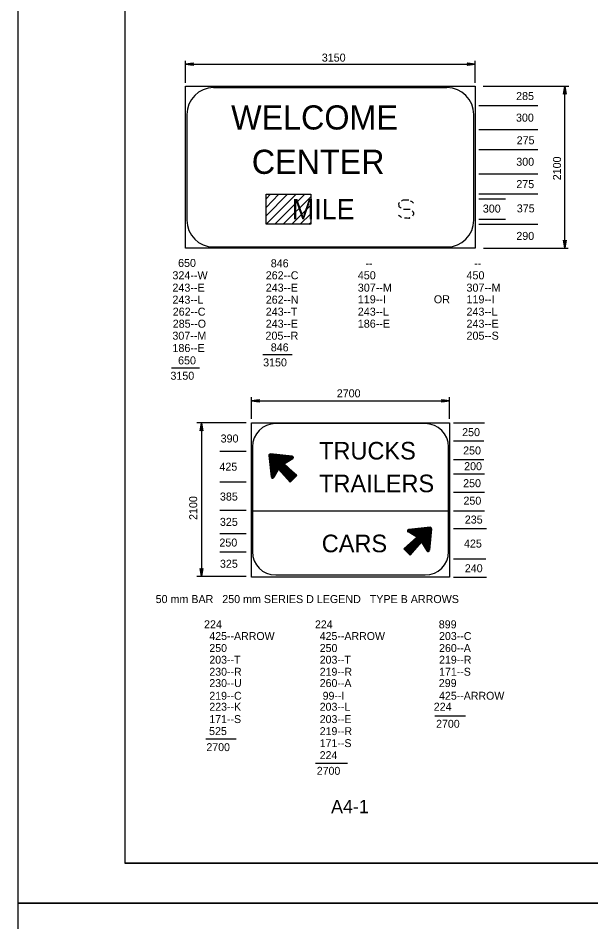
# Model space of a CAD drawing. Extents: x 638689 to 652291, y 298458 to 299646.
# Drawn here: x 651386.3 to 651601.1, y 299044.7 to 299383.4 of the extents above; entities that cross this region are included whole.
import ezdxf

# ---------------------------------------------------------------- set-up
doc = ezdxf.new("R2010")
doc.units = 0
for name, color, linetype in [('1', 7, 'Continuous'), ('2', 7, 'Continuous'), ('3', 7, 'Continuous'), ('PLT-BNDY', 7, 'Continuous')]:
    doc.layers.add(name, color=color, linetype=linetype)

# ---------------------------------------------------------------- blocks, each defined once
blk = doc.blocks.new('RARROW')
at = {"layer": '3'}
blk.add_lwpolyline([(-2.2695, 0.285), (-2.184875, 0.12075), (0, 0), (-2.2695, 0.285), (-2.38575, 0.384625), (0, 0), (-2.183125, -0.108), (-2.262875, -0.2705), (0, 0), (-2.38575, -0.379125), (-2.262875, -0.2705)], dxfattribs=at)

msp = doc.modelspace()

# ---------------------------------------------------------------- linework, layer by layer
at = {"layer": '1'}
for p, q in [((651426.31, 299630.75), (651426.31, 299066.75)), ((652212.31, 299066.75), (651426.31, 299066.75)), ((651426.31, 299066.75), (652012.31, 299066.75))]:
    msp.add_line(p, q, dxfattribs=at)
at = {"layer": '2'}
for p, q in [((651449.06, 299359.12), (651449.06, 299367.37)), ((651557.69, 299359.12), (651557.69, 299367.37)), ((651449.06, 299366.12), (651557.69, 299366.12)), ((651449.06, 299357.87), (651557.69, 299357.87)), ((651449.06, 299297.12), (651449.06, 299357.87)), ((651547.06, 299357.25), (651459.56, 299357.25)), ((651557.69, 299357.87), (651557.69, 299297.12)), ((651560.69, 299357.87), (651592.75, 299357.87)), ((651591.25, 299297.12), (651591.25, 299357.87)), ((651559.06, 299350.62), (651581.16, 299350.62)), ((651449.56, 299347.12), (651449.56, 299307.75)), ((651557.19, 299307.75), (651557.19, 299347.12)), ((651559.06, 299341.62), (651581.16, 299341.62)), ((651559.06, 299334.12), (651581.16, 299334.12)), ((651559.06, 299325), (651581.16, 299325)), ((651559.06, 299317.5), (651581.16, 299317.5)), ((651559.06, 299315.62), (651569.06, 299315.62)), ((651559.06, 299308), (651569.06, 299308)), ((651559.06, 299306.12), (651581.16, 299306.12)), ((651557.69, 299297.12), (651449.06, 299297.12)), ((651459.56, 299297.62), (651547.06, 299297.62)), ((651560.81, 299297.12), (651592.5, 299297.12)), ((651473.8, 299223.87), (651473.8, 299229.37)), ((651471.8, 299220.99), (651461.92, 299220.99)), ((651471.8, 299209.49), (651461.92, 299209.49)), ((651473.8, 299197.37), (651473.8, 299200.99)), ((651471.8, 299198.87), (651461.92, 299198.87)), ((651473.8, 299198.74), (651547.67, 299198.74)), ((651471.8, 299190.12), (651461.92, 299190.12)), ((651471.8, 299183.24), (651461.92, 299183.24)), ((651542.55, 299121.99), (651554.05, 299121.99)), ((651456.67, 299113.37), (651468.05, 299113.37)), ((651497.8, 299104.24), (651509.8, 299104.24))]:
    msp.add_line(p, q, dxfattribs=at)
msp.add_lwpolyline([(651479.31, 299306.12), (651479.31, 299317.37), (651496.06, 299317.37), (651496.06, 299306.12)], close=True, dxfattribs=at)
for points in [[(651479.31, 299306.12), (651490.56, 299317.37)], [(651479.31, 299309.25), (651487.31, 299317.37)], [(651479.31, 299312.37), (651484.06, 299317.37)], [(651479.31, 299315.62), (651480.94, 299317.37)], [(651482.56, 299306.12), (651493.81, 299317.37)], [(651485.69, 299306.12), (651496.06, 299316.37)], [(651488.94, 299306.12), (651496.06, 299313.25)], [(651492.06, 299306.12), (651496.06, 299310)], [(651495.31, 299306.12), (651496.06, 299306.75)], [(651473.8, 299231.74), (651548.05, 299231.74), (651548.05, 299226.62), (651548.05, 299219.99), (651548.05, 299214.99), (651548.05, 299208.37), (651548.05, 299203.24), (651548.05, 299198.37), (651548.05, 299187.37), (651548.05, 299173.87), (651473.8, 299173.87), (651473.8, 299189.37), (651473.8, 299196.12), (651473.8, 299203.24), (651473.8, 299211.87), (651473.8, 299222.62), (651473.8, 299231.74)]]:
    msp.add_lwpolyline(points, dxfattribs=at)
for centre, start, end in [((651459.64, 299347.25), 90, 180), ((651547.12, 299347.25), 0, 90), ((651459.64, 299307.66), 180, 270), ((651547.12, 299307.66), 270, 0)]:
    msp.add_arc(centre, 10.05, start, end, dxfattribs=at)
for points in [[(651529.31, 299314.25), (651529.19, 299314.12), (651529.06, 299314), (651529.06, 299313.12), (651529.19, 299312.62), (651529.69, 299312.37), (651529.94, 299312.12)], [(651532.81, 299315.12), (651532.56, 299315.12), (651532.19, 299315.12), (651530.94, 299315.12), (651530.69, 299315.12), (651530.06, 299314.75)], [(651534.56, 299314), (651534.06, 299314.5), (651533.44, 299314.75)], [(651530.06, 299308.62), (651529.94, 299308.75), (651529.56, 299309), (651528.94, 299309.5)], [(651530.81, 299311.75), (651531.19, 299311.75), (651531.69, 299311.75), (651532.31, 299311.75), (651532.81, 299311.75), (651533.19, 299311.75), (651533.31, 299311.62)], [(651534.06, 299311.12), (651534.31, 299310.87), (651534.44, 299310.62), (651534.56, 299310.5), (651534.56, 299310), (651534.44, 299309.62), (651534.19, 299309.12)], [(651533.06, 299308.37), (651533.19, 299308.5), (651532.81, 299308.37), (651532.19, 299308.37), (651531.56, 299308.37), (651531.19, 299308.37)]]:
    msp.add_spline(points, degree=3, dxfattribs=at)
at = {"layer": '3'}
for p, q in [((651478.06, 299257.37), (651489.06, 299257.37)), ((651443.81, 299252.37), (651454.31, 299252.37)), ((651473.8, 299233.24), (651473.8, 299241.37)), ((651548.05, 299233.24), (651548.05, 299241.37)), ((651473.8, 299239.99), (651548.05, 299239.99)), ((651471.8, 299231.74), (651453.3, 299231.74)), ((651455.05, 299231.74), (651455.05, 299174.12)), ((651549.55, 299231.74), (651561.14, 299231.74)), ((651549.55, 299224.99), (651560.94, 299224.99)), ((651474.17, 299222.62), (651474.17, 299183.37)), ((651547.67, 299183.37), (651547.67, 299222.62)), ((651480.3, 299219.49), (651481.17, 299211.49)), ((651480.42, 299219.87), (651480.42, 299219.87)), ((651480.42, 299219.87), (651480.42, 299219.87)), ((651489.05, 299219.24), (651480.92, 299220.12)), ((651480.92, 299219.62), (651480.92, 299219.62)), ((651486.05, 299216.37), (651489.3, 299218.37)), ((651488.8, 299218.74), (651488.8, 299218.74)), ((651489.67, 299218.74), (651489.67, 299218.74)), ((651489.67, 299218.74), (651489.67, 299218.74)), ((651549.55, 299217.99), (651560.94, 299217.99)), ((651483.92, 299214.37), (651482.17, 299211.24)), ((651483.92, 299214.37), (651483.92, 299214.37)), ((651483.92, 299214.37), (651488.3, 299209.49)), ((651485.05, 299215.37), (651485.05, 299215.37)), ((651486.05, 299216.37), (651486.05, 299216.37)), ((651490.8, 299211.99), (651486.05, 299216.37)), ((651481.8, 299211.49), (651481.8, 299211.49)), ((651481.8, 299210.74), (651481.8, 299210.74)), ((651481.8, 299210.74), (651481.8, 299210.74)), ((651488.3, 299209.49), (651490.8, 299211.99)), ((651490.8, 299211.99), (651490.8, 299211.99)), ((651549.55, 299212.62), (651561.14, 299212.62)), ((651488.3, 299209.49), (651488.3, 299209.49)), ((651549.55, 299205.74), (651561.14, 299205.74)), ((651549.55, 299198.74), (651561.14, 299198.74)), ((651532.17, 299191.12), (651532.17, 299191.12)), ((651532.17, 299191.12), (651532.17, 299191.12)), ((651535.8, 299188.87), (651532.55, 299190.87)), ((651540.8, 299192.62), (651532.8, 299191.74)), ((651532.8, 299191.12), (651532.8, 299191.12)), ((651540.67, 299183.99), (651541.42, 299191.99)), ((651540.8, 299191.99), (651540.8, 299191.99)), ((651549.55, 299192.12), (651561.9, 299192.12)), ((651535.8, 299188.87), (651530.92, 299184.49)), ((651533.3, 299182.12), (651537.55, 299186.99)), ((651535.8, 299188.87), (651535.8, 299188.87)), ((651536.67, 299187.87), (651536.67, 299187.87)), ((651537.55, 299186.99), (651537.55, 299186.99)), ((651537.55, 299186.99), (651539.55, 299183.74)), ((651530.92, 299184.49), (651530.92, 299184.49)), ((651530.92, 299184.49), (651533.3, 299182.12)), ((651540.05, 299184.12), (651540.05, 299184.12)), ((651540.05, 299183.37), (651540.05, 299183.37)), ((651540.05, 299183.37), (651540.05, 299183.37)), ((651533.3, 299182.12), (651533.3, 299182.12)), ((651549.55, 299180.74), (651561.71, 299180.74)), ((651471.8, 299174.12), (651453.3, 299174.12)), ((651549.55, 299173.87), (651561.9, 299173.87))]:
    msp.add_line(p, q, dxfattribs=at)
for points in [[(651538.92, 299231.49), (651483.05, 299231.49)], [(651480.67, 299219.62), (651481.42, 299211.62), (651481.42, 299211.24), (651481.92, 299210.99), (651482.05, 299211.24), (651483.92, 299214.87), (651484.3, 299214.62), (651488.42, 299209.87), (651490.67, 299212.12), (651485.8, 299216.24), (651485.92, 299216.49), (651489.3, 299218.49), (651489.55, 299218.74), (651489.42, 299218.99), (651489.05, 299218.99), (651480.92, 299219.87), (651480.67, 299219.87), (651480.67, 299219.62), (651480.8, 299219.62), (651481.8, 299211.24), (651483.92, 299214.99), (651488.42, 299210.12), (651490.42, 299211.99), (651485.55, 299216.49), (651489.42, 299218.74), (651480.8, 299219.74), (651481.92, 299211.74), (651483.92, 299215.24), (651488.42, 299210.24), (651490.3, 299211.99), (651485.3, 299216.49), (651489.05, 299218.74), (651480.92, 299219.62), (651481.92, 299211.99), (651483.92, 299215.37), (651488.55, 299210.49), (651490.05, 299211.99), (651485.17, 299216.49), (651488.55, 299218.74), (651481.05, 299219.49), (651481.92, 299212.49), (651483.92, 299215.37), (651488.55, 299210.74), (651489.8, 299211.99), (651485.05, 299216.62), (651488.3, 299218.62), (651481.17, 299219.24), (651482.05, 299212.87), (651483.92, 299215.49), (651488.55, 299210.99), (651489.67, 299212.12), (651484.92, 299216.62), (651487.92, 299218.37), (651481.42, 299218.99), (651482.3, 299213.24), (651483.92, 299215.62), (651488.55, 299211.24), (651489.55, 299212.12), (651484.92, 299216.62), (651487.42, 299218.12), (651481.55, 299218.99), (651482.42, 299213.87), (651483.92, 299215.99), (651488.55, 299211.49), (651489.3, 299212.12), (651484.8, 299216.62), (651487.17, 299217.99), (651481.8, 299218.74), (651482.55, 299214.24), (651483.8, 299216.24), (651488.55, 299211.74), (651489.05, 299212.12), (651484.55, 299216.62), (651486.67, 299217.87), (651481.92, 299218.62), (651482.55, 299214.49), (651483.8, 299216.37), (651488.55, 299211.87), (651488.8, 299212.12), (651484.42, 299216.62), (651486.17, 299217.87), (651482.17, 299218.49), (651482.55, 299214.99), (651483.8, 299216.62), (651488.55, 299211.99), (651488.55, 299211.99), (651484.17, 299216.62), (651485.8, 299217.74), (651482.42, 299218.12), (651482.67, 299215.37), (651483.8, 299216.62), (651488.55, 299211.99), (651483.92, 299216.74), (651485.42, 299217.74), (651482.55, 299217.99), (651482.8, 299215.62), (651483.8, 299216.74), (651486.05, 299214.62), (651483.8, 299216.87), (651485.17, 299217.62), (651482.67, 299217.87)], [(651482.67, 299217.87), (651483.05, 299216.24), (651484.92, 299217.49), (651482.8, 299217.74), (651483.17, 299216.49), (651484.67, 299217.49), (651483.05, 299217.49), (651483.17, 299216.62), (651484.17, 299217.49), (651483.17, 299217.49), (651483.17, 299216.87), (651483.8, 299217.37), (651483.17, 299217.37), (651483.3, 299217.37), (651483.55, 299217.37)], [(651540.8, 299192.37), (651532.92, 299191.49), (651532.55, 299191.49), (651532.42, 299191.12), (651532.55, 299190.99), (651536.05, 299188.87), (651536.05, 299188.87), (651531.17, 299184.49), (651533.42, 299182.24), (651537.42, 299186.99), (651537.67, 299186.99), (651539.67, 299183.74), (651540.05, 299183.49), (651540.17, 299183.74), (651540.3, 299183.99), (651541.17, 299192.12), (651541.17, 299192.24), (651540.92, 299192.49), (651540.8, 299192.12), (651532.55, 299191.24), (651536.3, 299188.87), (651531.3, 299184.49), (651533.3, 299182.24), (651537.67, 299187.49), (651540.05, 299183.74), (651541.05, 299192.24), (651532.92, 299191.12), (651536.42, 299188.87), (651531.55, 299184.49), (651533.3, 299182.74), (651537.67, 299187.62), (651539.92, 299184.12), (651540.8, 299191.99), (651533.3, 299191.12), (651536.55, 299188.87), (651531.8, 299184.49), (651533.3, 299182.99), (651537.67, 299187.74), (651539.92, 299184.37), (651540.8, 299191.74), (651533.67, 299190.99), (651536.67, 299188.99), (651532.17, 299184.49), (651533.3, 299183.24), (651537.67, 299187.87), (651539.8, 299184.62), (651540.67, 299191.74), (651534.17, 299190.99), (651537.05, 299188.99), (651532.42, 299184.49), (651533.42, 299183.37), (651537.67, 299188.12), (651539.55, 299185.12), (651540.3, 299191.49), (651534.8, 299190.87), (651537.17, 299188.99), (651532.55, 299184.49), (651533.42, 299183.49), (651537.67, 299188.12), (651539.55, 299185.49), (651540.17, 299191.37), (651535.17, 299190.62), (651537.3, 299188.99), (651532.8, 299184.49), (651533.42, 299183.87), (651537.8, 299188.24), (651539.55, 299185.87), (651540.05, 299191.24), (651535.42, 299190.49), (651537.42, 299188.99), (651532.92, 299184.49), (651533.42, 299184.12), (651537.8, 299188.49), (651539.42, 299186.37), (651539.8, 299191.12), (651535.92, 299190.49), (651537.55, 299188.99), (651533.05, 299184.49), (651533.42, 299184.12), (651537.8, 299188.74), (651539.17, 299186.74), (651539.67, 299190.99), (651536.3, 299190.49), (651537.67, 299188.99), (651533.3, 299184.49), (651533.3, 299184.24), (651537.92, 299188.87), (651539.05, 299187.24), (651539.55, 299190.62), (651536.67, 299190.37), (651537.8, 299189.12), (651533.3, 299184.37), (651538.17, 299188.99), (651539.05, 299187.62), (651539.55, 299190.49), (651537.17, 299190.24), (651538.17, 299189.12), (651536.05, 299186.99), (651538.3, 299189.12), (651538.92, 299187.74), (651539.42, 299190.37)], [(651539.42, 299190.37), (651537.42, 299190.12), (651538.8, 299188.12), (651539.05, 299190.24), (651537.67, 299189.99), (651538.8, 299188.24), (651538.8, 299189.99), (651537.92, 299189.87), (651538.67, 299188.87), (651538.67, 299189.87), (651538.3, 299189.74), (651538.55, 299188.99), (651538.55, 299189.74), (651538.55, 299189.74), (651538.55, 299189.37)], [(651483.05, 299174.74), (651538.92, 299174.74)]]:
    msp.add_lwpolyline(points, dxfattribs=at)
for centre, radius, start, end in [((651482.9, 299222.71), 8.75, 90, 180), ((651538.97, 299222.71), 8.75, 0, 90), ((651480.86, 299219.56), 0.515, 84.0498, 185.9502), ((651488.94, 299218.72), 0.515, 301.5539, 84.0498), ((651481.7, 299211.48), 0.515, 185.9502, 328.4461), ((651532.78, 299191.24), 0.515, 95.9502, 238.4461), ((651540.86, 299192.08), 0.515, 354.0498, 95.9502), ((651482.9, 299183.47), 8.75, 180, 270), ((651538.97, 299183.47), 8.75, 270, 0), ((651540.02, 299183.99), 0.515, 211.5539, 354.0498)]:
    msp.add_arc(centre, radius, start, end, dxfattribs=at)
at = {"layer": 'PLT-BNDY'}
for points in [[(651386.31, 299645.75), (652227.31, 299645.75), (652227.31, 299051.75), (651386.31, 299051.75)], [(651386.31, 299051.75), (652227.31, 299051.75), (652227.31, 298457.75), (651386.31, 298457.75)]]:
    msp.add_lwpolyline(points, close=True, dxfattribs=at)

# ---------------------------------------------------------------- block references
at = {"layer": '2', "xscale": 1.2574347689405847, "yscale": 1.3092961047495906}
for p, rotation in [((651449.06, 299366.12), 180), ((651591.25, 299357.87), 89.99999999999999), ((651591.25, 299297.12), -90.00000000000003), ((651473.8, 299239.99), 180), ((651455.05, 299231.74), 89.99999999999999), ((651455.05, 299174.12), -90.00000000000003)]:
    msp.add_blockref('RARROW', p, dxfattribs=dict(at, rotation=rotation))
for p in [(651557.69, 299366.12), (651548.05, 299239.99)]:
    msp.add_blockref('RARROW', p, dxfattribs=at)

# ---------------------------------------------------------------- texts
at = {"layer": '2'}
for s, height, p in [('3150', 3, (651500.19, 299367.06)), ('285', 3, (651573.04, 299352.66)), ('WELCOME', 9.049, (651466.19, 299341.62)), ('300', 3, (651572.99, 299344.57)), ('275', 3, (651573.25, 299336.09)), ('CENTER', 9.049, (651473.94, 299325)), ('300', 3, (651573.1, 299328.04)), ('275', 3, (651573.11, 299319.66)), ('   MILE', 7.54, (651480.56, 299308)), ('300', 3, (651560.56, 299310.5)), ('375', 3, (651573.29, 299310.57)), ('290', 3, (651573.12, 299300.26)), ('650', 3, (651446.31, 299290.12)), ('846', 3, (651481.06, 299290)), (' 324--W', 3.016, (651443.06, 299285.5)), (' 262--C', 3, (651478.06, 299285.5)), (' 450   ', 3.016, (651512.56, 299285.5)), ('     -- ', 3.016, (651510.94, 299290)), (' 450   ', 3.016, (651553.31, 299285.5)), ('     -- ', 3.016, (651551.69, 299290)), (' 243--E', 3.016, (651443.06, 299280.87)), (' 243--E', 3, (651478.06, 299280.87)), (' 307--M', 3.016, (651512.56, 299280.87)), (' 307--M', 3.016, (651553.31, 299280.87)), (' 243--L', 3.016, (651443.06, 299276.37)), (' 262--N', 3, (651478.06, 299276.37)), (' 119--I', 3.016, (651512.56, 299276.5)), ('OR', 3.016, (651542.19, 299276.5)), (' 119--I', 3.016, (651553.31, 299276.5)), (' 262--C', 3, (651443.19, 299271.87)), (' 243--T', 3, (651478.06, 299271.87)), (' 243--L', 3.016, (651512.56, 299271.87)), (' 243--L', 3.016, (651553.31, 299271.87)), (' 285--O', 3, (651443.19, 299267.37)), (' 243--E', 3, (651478.06, 299267.37)), (' 186--E', 3.016, (651512.56, 299267.37)), (' 243--E', 3.016, (651553.31, 299267.37)), (' 307--M', 3, (651443.06, 299262.87)), (' 205--R', 3.016, (651477.94, 299262.87)), (' 205--S', 3.016, (651553.31, 299262.87)), (' 186--E', 3.016, (651443.06, 299258.25)), ('846', 3, (651481.06, 299258.5)), ('650', 3, (651446.31, 299253.62)), ('3150', 3, (651478.19, 299252.87)), ('3150', 3, (651443.44, 299247.87)), ('A4-1', 5, (651503.67, 299085.48))]:
    msp.add_text(s, height=height, dxfattribs=at).set_placement(p)
msp.add_text('2100', height=3, rotation=90, dxfattribs=at).set_placement((651589.85, 299322.6))
at = {"layer": '3'}
for s, height, p in [('2700', 3, (651505.8, 299241.28)), ('390', 3, (651462.26, 299224.36)), ('250', 3, (651552.8, 299226.74)), ('TRUCKS', 6.596, (651499.17, 299217.99)), ('250', 3, (651553.17, 299219.87)), ('425', 3, (651461.81, 299213.8)), ('200', 3, (651553.55, 299213.99)), ('TRAILERS', 6.596, (651499.17, 299205.74)), ('250', 3, (651553.17, 299207.62)), ('385', 3, (651462, 299202.61)), ('250', 3, (651553.29, 299201.06)), ('235', 3, (651553.8, 299193.99)), ('325', 3, (651461.99, 299193.12)), ('250', 3, (651461.8, 299185.37)), ('CARS', 6.596, (651500.17, 299183.24)), ('425', 3, (651553.49, 299184.99)), ('325', 3, (651462, 299177.43)), ('240', 3, (651553.8, 299175.74)), ('50 mm BAR   250 mm SERIES D LEGEND   TYPE B ARROWS', 3, (651437.9, 299164.2)), ('  224        ', 3, (651453.8, 299154.74)), ('  224        ', 2.9663, (651495.42, 299154.74)), (' 899       ', 3, (651542.92, 299154.74)), (' 425--ARROW', 2.9663, (651456.92, 299150.37)), (' 425--ARROW', 2.9663, (651498.3, 299150.37)), (' 203--C    ', 2.9663, (651543.05, 299150.37)), (' 250       ', 2.9663, (651456.92, 299145.87)), (' 250       ', 2.9663, (651498.3, 299145.87)), (' 260--A    ', 2.9663, (651543.05, 299145.87)), (' 203--T    ', 2.9663, (651456.92, 299141.49)), (' 203--T    ', 2.9663, (651498.3, 299141.49)), (' 219--R    ', 2.9663, (651543.05, 299141.49)), (' 230--R    ', 2.9663, (651456.92, 299136.99)), (' 219--R    ', 2.9663, (651498.3, 299136.99)), (' 171--S    ', 2.9663, (651543.05, 299136.99)), (' 230--U    ', 2.9663, (651456.92, 299132.74)), (' 260--A    ', 2.9663, (651498.3, 299132.74)), (' 299       ', 3, (651542.92, 299132.74)), (' 219--C    ', 2.9663, (651456.92, 299127.99)), ('  99--I    ', 2.9663, (651498.3, 299127.99)), (' 425--ARROW', 2.9663, (651543.05, 299127.99)), (' 223--K    ', 2.9663, (651456.92, 299123.87)), (' 203--L    ', 2.9663, (651498.3, 299123.87)), ('  224        ', 3, (651539.92, 299123.87)), (' 171--S    ', 2.9663, (651456.92, 299119.24)), (' 203--E    ', 2.9663, (651498.3, 299119.24)), ('2700       ', 2.9663, (651543.05, 299117.49)), (' 525       ', 3, (651456.8, 299114.74)), (' 219--R    ', 2.9663, (651498.3, 299114.74)), (' 171--S    ', 2.9663, (651498.3, 299110.24)), ('2700       ', 2.9663, (651456.92, 299108.74)), (' 224       ', 2.9663, (651498.3, 299105.74)), ('2700        ', 2.9663, (651498.3, 299099.87))]:
    msp.add_text(s, height=height, dxfattribs=at).set_placement(p)
msp.add_text('2100', height=3, rotation=90, dxfattribs=at).set_placement((651453.47, 299195.34))

doc.saveas('drawing.dxf')
